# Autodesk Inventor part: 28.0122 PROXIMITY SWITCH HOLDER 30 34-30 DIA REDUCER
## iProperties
Created: 2007-05
Part Number: 28.0122 PROXIMITY SWITCH HOLDER 30 34-30 DIA REDUCER
Document SubType Name: Modeling
Designer: Andy Moles
Material: Acetal Resin, Black
Density: 1.425 g/cm^3
Author: Andy Moles
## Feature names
1. Extrusion1
